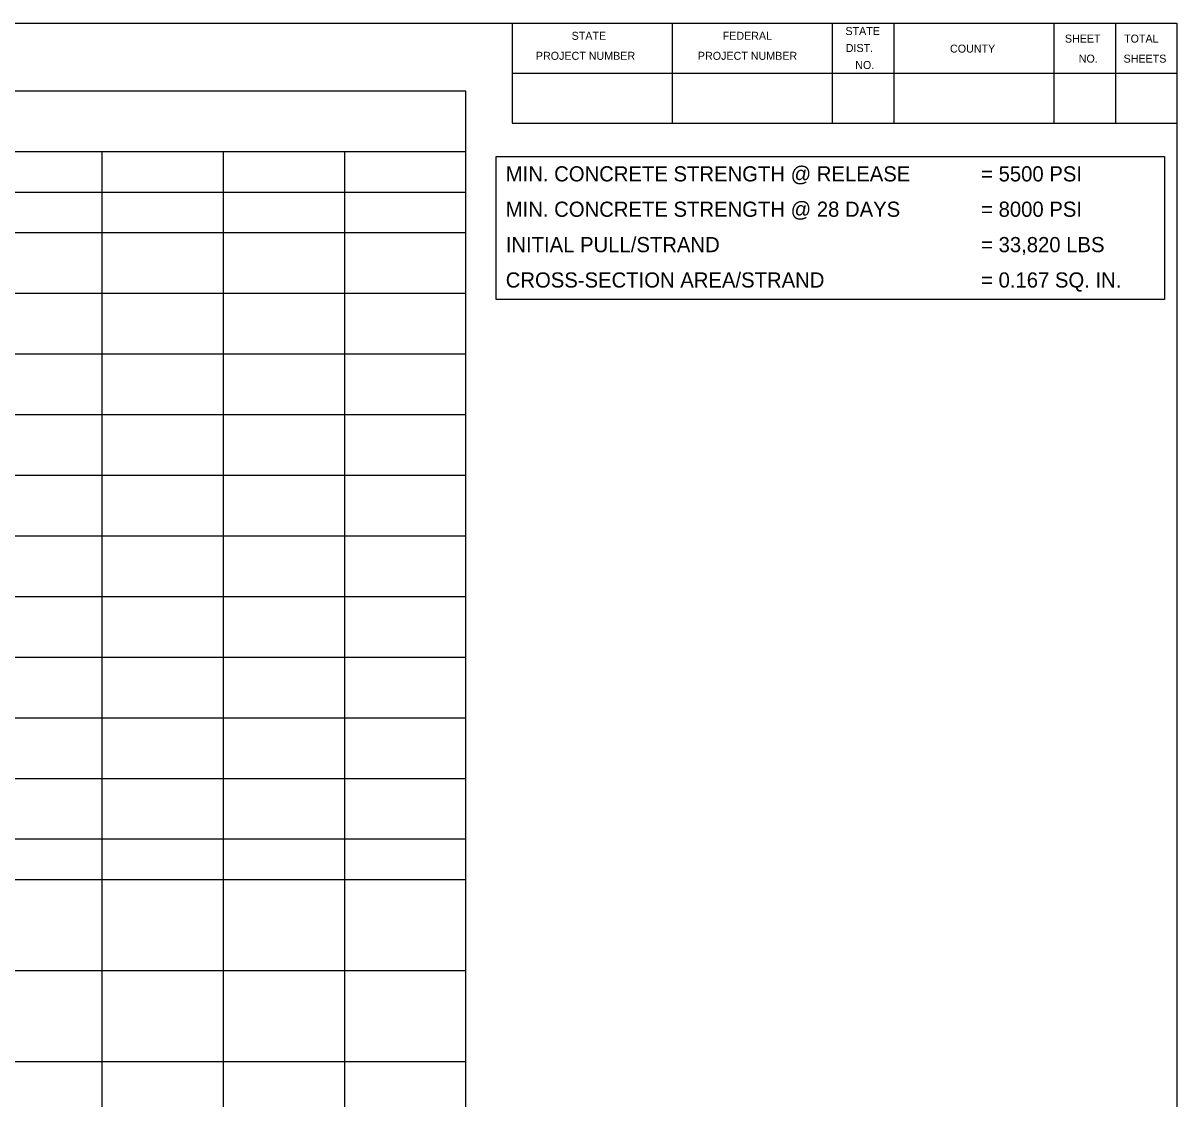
# Model space of a CAD drawing. Extents: x 762.3 to 790.4, y -1210.3 to -1192.2.
# Drawn here: x 780.44 to 789.95, y -1201.48 to -1192.61 of the extents above; entities that cross this region are included whole.
import ezdxf

# ---------------------------------------------------------------- set-up
doc = ezdxf.new("R2010")
doc.units = 0
doc.layers.add('Default', color=7, linetype='Continuous')

msp = doc.modelspace()

# ---------------------------------------------------------------- linework, layer by layer
at = {"layer": 'Default'}
for p, q in [((763.5542, -1192.6096), (789.9542, -1192.6096)), ((784.4721, -1192.6096), (784.4721, -1193.4346)), ((785.7921, -1192.6096), (785.7921, -1193.4346)), ((787.1121, -1192.6096), (787.1121, -1193.4346)), ((787.6195, -1192.6096), (787.6195, -1193.4346)), ((788.9395, -1192.6096), (788.9395, -1193.4346)), ((789.4469, -1192.6096), (789.4469, -1193.4346)), ((789.9542, -1192.6096), (789.9542, -1209.9346)), ((784.4721, -1193.0221), (789.9542, -1193.0221)), ((764.5075, -1193.1689), (784.0909, -1193.1689)), ((784.0909, -1205.3356), (784.0909, -1193.1689)), ((784.4721, -1193.4346), (789.9542, -1193.4346)), ((764.5075, -1193.6689), (784.0909, -1193.6689)), ((781.0909, -1205.3356), (781.0909, -1193.6689)), ((782.0909, -1205.3356), (782.0909, -1193.6689)), ((783.0909, -1205.3356), (783.0909, -1193.6689)), ((764.5075, -1194.0023), (784.0909, -1194.0023)), ((764.5075, -1194.3356), (784.0909, -1194.3356)), ((764.5075, -1194.8356), (784.0909, -1194.8356)), ((767.1979, -1195.3356), (784.0909, -1195.3356)), ((767.1979, -1195.8356), (784.0909, -1195.8356)), ((767.1979, -1196.3356), (784.0909, -1196.3356)), ((767.1979, -1196.8356), (784.0909, -1196.8356)), ((764.5075, -1197.3356), (784.0909, -1197.3356)), ((764.5075, -1197.8356), (784.0909, -1197.8356)), ((764.5075, -1198.3356), (784.0909, -1198.3356)), ((764.5075, -1198.8356), (784.0909, -1198.8356)), ((764.5075, -1199.3356), (784.0909, -1199.3356)), ((764.5075, -1199.6689), (784.0909, -1199.6689)), ((767.1979, -1200.4189), (784.0909, -1200.4189)), ((764.5075, -1201.1689), (784.0909, -1201.1689))]:
    msp.add_line(p, q, dxfattribs=at)
msp.add_lwpolyline([(784.3406, -1193.709), (789.8529, -1193.709), (789.8529, -1194.8874), (784.3406, -1194.8874)], close=True, dxfattribs=at)

# ---------------------------------------------------------------- texts
for s, height, p in [('STATE', 0.066, (787.2201, -1192.7076)), ('STATE', 0.066, (784.9621, -1192.7474)), ('FEDERAL ', 0.066, (786.2079, -1192.7474)), ('SHEET ', 0.066, (789.0304, -1192.7705)), ('TOTAL ', 0.066, (789.5184, -1192.7705)), ('PROJECT NUMBER', 0.066, (784.6672, -1192.9124)), ('PROJECT NUMBER', 0.066, (786.0035, -1192.9124)), ('DIST. ', 0.066, (787.223, -1192.8478)), ('COUNTY', 0.066, (788.083, -1192.853)), ('NO.', 0.066, (787.3012, -1192.9881)), ('NO.', 0.066, (789.1444, -1192.9355)), ('SHEETS', 0.066, (789.5142, -1192.9355)), ('MIN. CONCRETE STRENGTH @ RELEASE', 0.125, (784.4188, -1193.9148)), ('= 5500 PSI', 0.125, (788.3394, -1193.9148)), ('MIN. CONCRETE STRENGTH @ 28 DAYS', 0.125, (784.4188, -1194.2065)), ('= 8000 PSI', 0.125, (788.3394, -1194.2065)), ('INITIAL PULL/STRAND', 0.125, (784.4188, -1194.4982)), ('= 33,820 LBS', 0.125, (788.3394, -1194.4982)), ('CROSS-SECTION AREA/STRAND', 0.125, (784.4188, -1194.7898)), ('= 0.167 SQ. IN.', 0.125, (788.3394, -1194.7898))]:
    msp.add_text(s, height=height, dxfattribs=at).set_placement(p)

doc.saveas('drawing.dxf')
